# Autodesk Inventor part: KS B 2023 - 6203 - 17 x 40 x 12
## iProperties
IsCustomPart: 0
Created: 2009-02
Part Number: KS B 2023 - 6203 - 17 x 40 x 12
Material: Steel, Mild
Description: 깊은 그루브 볼 베어링
Document SubType Name: Modeling
Standard: KS B 2023
Designer: SeoGD™ [www.esajin.kr]
Standards Organization: KS
Language: ko-KR
Size Designation: 6203 - 17 x 40 x 12
Categories: <MemberInstance><Categories><Category DisplayName="샤프트 부품" InternalName="7f7aeb1f-a693-4053-b835-cee3144e0d98" Mnemonic="SHFT"><Category DisplayName="베어링" Inter
Density: 1 g/cm^3
Author: SeoGD™ [www.esajin.kr]
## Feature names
1. IDS_ARRAYBALL[SIMPL:T] [Circular Pattern]
